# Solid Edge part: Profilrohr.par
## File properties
Username: bmolnar
Dokumentum tartalom típus: 0
Author: bmolnar
Last saved by: bmolnar
Revision: 96
Sűrűség: 0,000 kg/m^3
Pontosság: 0,990
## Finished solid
Body 1: solid body, 179 faces, 530 edges, 352 vertices.
  Faces by surface: cylinder 109, plane 70
  Edges by curve: line 312, circle 218
Bounding box of the edges (mm): 105.500 x 105.500 x 2557.000, from (-52.75, -52.75, -2516) to (52.75, 52.75, 41).
Cylindrical faces by radius (mm): R0.1 x16, R0.2 x30, R0.5 x28, R1 x10, R4.6 x8, R5.7 x4, R7.5 x4, R50 x1, R52.7 x8
Planar faces by outward normal: +x 6, +y 6, +z 1, -x 4, -y 4, -z 1, oblique 48
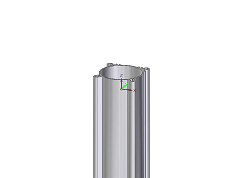
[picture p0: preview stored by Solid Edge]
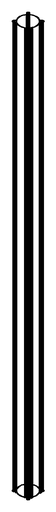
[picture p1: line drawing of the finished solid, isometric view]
